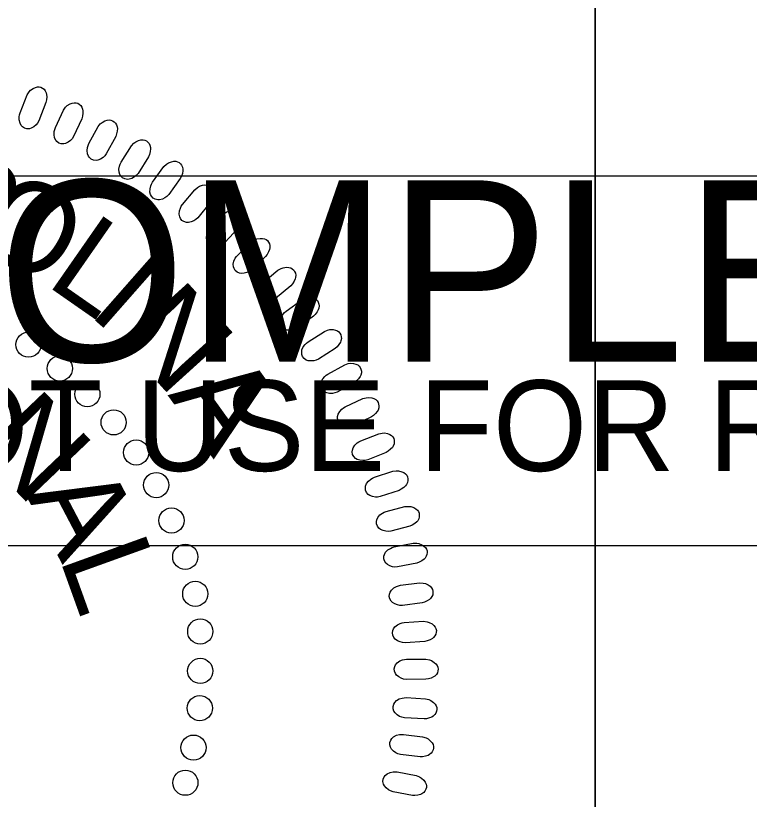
# Model space of a CAD drawing. Extents: x 505602 to 527661, y 418813 to 494436.
# Drawn here: x 507132.23 to 507178.88, y 484086.39 to 484136.19 of the extents above; entities that cross this region are included whole.
import ezdxf

# ---------------------------------------------------------------- set-up
doc = ezdxf.new("R2010")
doc.units = 0
for name, color, linetype in [('Sheet PE Seal Cell', 7, 'Continuous'), ('Sheet Profile CELL', 7, 'Continuous'), ('Sheet Sticker Incomplete CELL', 7, 'Continuous')]:
    doc.layers.add(name, color=color, linetype=linetype)

msp = doc.modelspace()

# ---------------------------------------------------------------- linework, layer by layer
at = {"layer": 'Sheet PE Seal Cell'}
for points in [[(507132.514, 484130.009), (507132.966, 484131.15), (507133.082, 484131.34), (507133.182, 484131.451), (507133.349, 484131.567), (507133.48, 484131.633), (507133.613, 484131.666), (507133.725, 484131.664), (507133.837, 484131.642), (507133.933, 484131.582), (507134.034, 484131.51), (507134.109, 484131.416), (507134.17, 484131.284), (507134.196, 484131.188), (507134.203, 484131.025), (507134.193, 484130.836), (507134.155, 484130.679), (507133.699, 484129.508), (507133.615, 484129.359), (507133.522, 484129.245), (507133.38, 484129.13), (507133.224, 484129.041), (507133.105, 484129.003), (507132.936, 484129.006), (507132.79, 484129.042), (507132.666, 484129.134), (507132.587, 484129.219), (507132.505, 484129.359), (507132.457, 484129.56), (507132.46, 484129.752), (507132.481, 484129.884)], [(507134.756, 484129.075), (507135.278, 484130.185), (507135.405, 484130.368), (507135.512, 484130.472), (507135.686, 484130.577), (507135.821, 484130.635), (507135.956, 484130.659), (507136.068, 484130.651), (507136.178, 484130.621), (507136.27, 484130.555), (507136.366, 484130.478), (507136.435, 484130.379), (507136.487, 484130.244), (507136.508, 484130.146), (507136.505, 484129.982), (507136.482, 484129.794), (507136.435, 484129.64), (507135.906, 484128.5), (507135.814, 484128.357), (507135.713, 484128.249), (507135.564, 484128.143), (507135.403, 484128.065), (507135.281, 484128.034), (507135.114, 484128.046), (507134.97, 484128.093), (507134.852, 484128.192), (507134.779, 484128.281), (507134.706, 484128.426), (507134.67, 484128.63), (507134.686, 484128.822), (507134.714, 484128.951)], [(507136.88, 484128.06), (507137.471, 484129.135), (507137.609, 484129.309), (507137.722, 484129.406), (507137.902, 484129.5), (507138.04, 484129.55), (507138.177, 484129.566), (507138.288, 484129.55), (507138.396, 484129.514), (507138.485, 484129.442), (507138.575, 484129.358), (507138.638, 484129.255), (507138.682, 484129.118), (507138.695, 484129.019), (507138.683, 484128.856), (507138.648, 484128.669), (507138.591, 484128.519), (507137.992, 484127.414), (507137.89, 484127.276), (507137.784, 484127.175), (507137.629, 484127.079), (507137.462, 484127.011), (507137.339, 484126.987), (507137.173, 484127.011), (507137.032, 484127.065), (507136.92, 484127.172), (507136.852, 484127.267), (507136.789, 484127.416), (507136.766, 484127.622), (507136.794, 484127.811), (507136.83, 484127.94)], [(507138.938, 484126.875), (507139.595, 484127.91), (507139.744, 484128.076), (507139.863, 484128.165), (507140.049, 484128.249), (507140.19, 484128.289), (507140.327, 484128.296), (507140.437, 484128.274), (507140.543, 484128.23), (507140.626, 484128.154), (507140.711, 484128.064), (507140.768, 484127.958), (507140.802, 484127.817), (507140.81, 484127.718), (507140.787, 484127.555), (507140.741, 484127.372), (507140.674, 484127.225), (507140.007, 484126.16), (507139.897, 484126.03), (507139.784, 484125.936), (507139.623, 484125.849), (507139.454, 484125.791), (507139.329, 484125.775), (507139.164, 484125.809), (507139.027, 484125.873), (507138.923, 484125.986), (507138.861, 484126.085), (507138.807, 484126.237), (507138.797, 484126.444), (507138.837, 484126.632), (507138.881, 484126.758)], [(507140.938, 484125.602), (507141.659, 484126.594), (507141.818, 484126.75), (507141.943, 484126.832), (507142.133, 484126.903), (507142.276, 484126.935), (507142.413, 484126.934), (507142.522, 484126.904), (507142.625, 484126.854), (507142.703, 484126.772), (507142.782, 484126.678), (507142.832, 484126.568), (507142.858, 484126.425), (507142.86, 484126.326), (507142.826, 484126.165), (507142.769, 484125.985), (507142.693, 484125.842), (507141.96, 484124.822), (507141.842, 484124.698), (507141.723, 484124.611), (507141.558, 484124.535), (507141.384, 484124.488), (507141.259, 484124.481), (507141.097, 484124.524), (507140.964, 484124.597), (507140.866, 484124.716), (507140.811, 484124.818), (507140.767, 484124.974), (507140.77, 484125.181), (507140.821, 484125.366), (507140.873, 484125.489)], [(507142.832, 484124.186), (507143.614, 484125.13), (507143.783, 484125.276), (507143.912, 484125.35), (507144.107, 484125.409), (507144.251, 484125.432), (507144.389, 484125.422), (507144.495, 484125.386), (507144.594, 484125.329), (507144.668, 484125.243), (507144.741, 484125.143), (507144.783, 484125.031), (507144.8, 484124.887), (507144.796, 484124.787), (507144.751, 484124.629), (507144.683, 484124.453), (507144.599, 484124.315), (507143.804, 484123.343), (507143.678, 484123.226), (507143.554, 484123.147), (507143.384, 484123.082), (507143.208, 484123.046), (507143.082, 484123.046), (507142.923, 484123.1), (507142.795, 484123.18), (507142.705, 484123.306), (507142.657, 484123.411), (507142.623, 484123.569), (507142.639, 484123.776), (507142.701, 484123.958), (507142.761, 484124.076)], [(507144.603, 484122.671), (507145.444, 484123.566), (507145.621, 484123.7), (507145.755, 484123.766), (507145.953, 484123.813), (507146.099, 484123.826), (507146.235, 484123.808), (507146.339, 484123.765), (507146.434, 484123.703), (507146.502, 484123.612), (507146.569, 484123.508), (507146.604, 484123.393), (507146.612, 484123.248), (507146.601, 484123.148), (507146.547, 484122.994), (507146.468, 484122.822), (507146.376, 484122.691), (507145.52, 484121.77), (507145.388, 484121.662), (507145.259, 484121.591), (507145.085, 484121.536), (507144.908, 484121.51), (507144.782, 484121.519), (507144.626, 484121.583), (507144.504, 484121.671), (507144.423, 484121.802), (507144.381, 484121.91), (507144.356, 484122.07), (507144.385, 484122.275), (507144.459, 484122.452), (507144.526, 484122.567)], [(507146.348, 484120.978), (507147.243, 484121.818), (507147.428, 484121.94), (507147.566, 484121.998), (507147.766, 484122.032), (507147.912, 484122.036), (507148.047, 484122.009), (507148.148, 484121.96), (507148.24, 484121.892), (507148.302, 484121.796), (507148.362, 484121.689), (507148.39, 484121.572), (507148.389, 484121.427), (507148.371, 484121.329), (507148.308, 484121.178), (507148.219, 484121.011), (507148.117, 484120.885), (507147.206, 484120.02), (507147.067, 484119.921), (507146.935, 484119.858), (507146.757, 484119.814), (507146.578, 484119.8), (507146.453, 484119.816), (507146.302, 484119.89), (507146.185, 484119.985), (507146.112, 484120.121), (507146.077, 484120.232), (507146.063, 484120.393), (507146.105, 484120.596), (507146.19, 484120.768), (507146.264, 484120.879)], [(507147.96, 484119.232), (507148.905, 484120.014), (507149.099, 484120.124), (507149.24, 484120.173), (507149.441, 484120.195), (507149.588, 484120.19), (507149.721, 484120.154), (507149.818, 484120.099), (507149.906, 484120.025), (507149.961, 484119.926), (507150.014, 484119.815), (507150.035, 484119.696), (507150.025, 484119.552), (507150.001, 484119.455), (507149.929, 484119.307), (507149.829, 484119.148), (507149.72, 484119.028), (507148.756, 484118.222), (507148.611, 484118.131), (507148.475, 484118.077), (507148.295, 484118.045), (507148.116, 484118.042), (507147.992, 484118.066), (507147.846, 484118.148), (507147.736, 484118.251), (507147.671, 484118.392), (507147.643, 484118.504), (507147.639, 484118.666), (507147.693, 484118.866), (507147.789, 484119.032), (507147.87, 484119.138)], [(507149.42, 484117.41), (507150.413, 484118.13), (507150.612, 484118.229), (507150.756, 484118.269), (507150.96, 484118.278), (507151.105, 484118.263), (507151.235, 484118.219), (507151.329, 484118.158), (507151.412, 484118.079), (507151.461, 484117.976), (507151.507, 484117.862), (507151.52, 484117.743), (507151.501, 484117.599), (507151.472, 484117.504), (507151.39, 484117.361), (507151.28, 484117.208), (507151.164, 484117.096), (507150.152, 484116.351), (507150.001, 484116.27), (507149.861, 484116.224), (507149.68, 484116.203), (507149.501, 484116.212), (507149.379, 484116.244), (507149.239, 484116.335), (507149.135, 484116.445), (507149.079, 484116.589), (507149.058, 484116.703), (507149.064, 484116.865), (507149.131, 484117.061), (507149.237, 484117.221), (507149.324, 484117.321)], [(507150.821, 484115.463), (507151.857, 484116.12), (507152.062, 484116.206), (507152.208, 484116.237), (507152.411, 484116.234), (507152.556, 484116.21), (507152.683, 484116.158), (507152.773, 484116.091), (507152.85, 484116.007), (507152.893, 484115.902), (507152.932, 484115.784), (507152.938, 484115.664), (507152.909, 484115.522), (507152.874, 484115.429), (507152.783, 484115.292), (507152.664, 484115.145), (507152.542, 484115.041), (507151.485, 484114.362), (507151.329, 484114.29), (507151.187, 484114.253), (507151.004, 484114.243), (507150.826, 484114.263), (507150.707, 484114.303), (507150.572, 484114.403), (507150.476, 484114.519), (507150.429, 484114.666), (507150.415, 484114.781), (507150.431, 484114.942), (507150.51, 484115.134), (507150.626, 484115.287), (507150.72, 484115.382)], [(507152.082, 484113.413), (507153.157, 484114.004), (507153.367, 484114.077), (507153.515, 484114.099), (507153.717, 484114.082), (507153.86, 484114.05), (507153.984, 484113.989), (507154.07, 484113.917), (507154.141, 484113.828), (507154.178, 484113.72), (507154.209, 484113.601), (507154.207, 484113.481), (507154.17, 484113.341), (507154.129, 484113.25), (507154.03, 484113.119), (507153.901, 484112.981), (507153.773, 484112.884), (507152.675, 484112.272), (507152.515, 484112.21), (507152.371, 484112.182), (507152.188, 484112.185), (507152.012, 484112.215), (507151.895, 484112.262), (507151.767, 484112.371), (507151.678, 484112.492), (507151.641, 484112.642), (507151.634, 484112.758), (507151.66, 484112.918), (507151.751, 484113.104), (507151.876, 484113.25), (507151.976, 484113.338)], [(507153.189, 484111.33), (507154.299, 484111.853), (507154.514, 484111.912), (507154.662, 484111.925), (507154.864, 484111.895), (507155.004, 484111.853), (507155.124, 484111.786), (507155.205, 484111.708), (507155.271, 484111.615), (507155.3, 484111.505), (507155.324, 484111.384), (507155.315, 484111.264), (507155.269, 484111.127), (507155.222, 484111.039), (507155.115, 484110.914), (507154.978, 484110.784), (507154.843, 484110.696), (507153.709, 484110.154), (507153.546, 484110.103), (507153.4, 484110.084), (507153.219, 484110.097), (507153.044, 484110.139), (507152.93, 484110.193), (507152.809, 484110.31), (507152.728, 484110.437), (507152.7, 484110.588), (507152.701, 484110.705), (507152.737, 484110.862), (507152.84, 484111.042), (507152.974, 484111.18), (507153.079, 484111.262)], [(507154.169, 484109.169), (507155.31, 484109.621), (507155.527, 484109.666), (507155.676, 484109.67), (507155.875, 484109.628), (507156.013, 484109.577), (507156.128, 484109.502), (507156.204, 484109.42), (507156.264, 484109.323), (507156.286, 484109.211), (507156.302, 484109.089), (507156.286, 484108.97), (507156.231, 484108.835), (507156.179, 484108.751), (507156.065, 484108.633), (507155.92, 484108.511), (507155.78, 484108.432), (507154.614, 484107.963), (507154.448, 484107.921), (507154.301, 484107.912), (507154.12, 484107.936), (507153.949, 484107.989), (507153.839, 484108.05), (507153.725, 484108.174), (507153.652, 484108.306), (507153.634, 484108.46), (507153.642, 484108.575), (507153.688, 484108.73), (507153.802, 484108.904), (507153.944, 484109.033), (507154.054, 484109.108)], [(507155.042, 484106.855), (507156.21, 484107.234), (507156.43, 484107.266), (507156.579, 484107.26), (507156.775, 484107.205), (507156.909, 484107.147), (507157.02, 484107.065), (507157.09, 484106.978), (507157.143, 484106.877), (507157.159, 484106.764), (507157.168, 484106.641), (507157.143, 484106.523), (507157.08, 484106.393), (507157.023, 484106.311), (507156.901, 484106.2), (507156.749, 484106.089), (507156.604, 484106.018), (507155.411, 484105.623), (507155.243, 484105.592), (507155.097, 484105.592), (507154.918, 484105.628), (507154.75, 484105.691), (507154.644, 484105.759), (507154.538, 484105.89), (507154.473, 484106.026), (507154.465, 484106.181), (507154.48, 484106.295), (507154.536, 484106.447), (507154.66, 484106.613), (507154.81, 484106.733), (507154.924, 484106.801)], [(507155.788, 484104.682), (507156.976, 484104.986), (507157.197, 484105.005), (507157.346, 484104.989), (507157.538, 484104.923), (507157.669, 484104.856), (507157.773, 484104.767), (507157.838, 484104.676), (507157.885, 484104.572), (507157.894, 484104.458), (507157.894, 484104.335), (507157.863, 484104.219), (507157.792, 484104.093), (507157.73, 484104.015), (507157.601, 484103.913), (507157.442, 484103.81), (507157.293, 484103.748), (507156.078, 484103.429), (507155.908, 484103.409), (507155.762, 484103.418), (507155.585, 484103.465), (507155.422, 484103.538), (507155.32, 484103.613), (507155.224, 484103.75), (507155.167, 484103.89), (507155.169, 484104.045), (507155.191, 484104.158), (507155.256, 484104.306), (507155.39, 484104.464), (507155.548, 484104.574), (507155.666, 484104.635)], [(507156.297, 484102.428), (507157.502, 484102.657), (507157.725, 484102.661), (507157.872, 484102.637), (507158.059, 484102.558), (507158.185, 484102.483), (507158.285, 484102.388), (507158.343, 484102.293), (507158.384, 484102.186), (507158.385, 484102.072), (507158.378, 484101.949), (507158.339, 484101.835), (507158.261, 484101.714), (507158.194, 484101.64), (507158.059, 484101.546), (507157.894, 484101.454), (507157.742, 484101.402), (507156.508, 484101.159), (507156.337, 484101.15), (507156.192, 484101.168), (507156.019, 484101.226), (507155.861, 484101.31), (507155.764, 484101.39), (507155.675, 484101.534), (507155.628, 484101.677), (507155.639, 484101.831), (507155.669, 484101.943), (507155.743, 484102.087), (507155.887, 484102.235), (507156.052, 484102.336), (507156.173, 484102.389)], [(507156.695, 484099.989), (507157.913, 484100.141), (507158.135, 484100.132), (507158.28, 484100.098), (507158.462, 484100.008), (507158.584, 484099.925), (507158.677, 484099.824), (507158.729, 484099.725), (507158.763, 484099.617), (507158.757, 484099.503), (507158.742, 484099.38), (507158.696, 484099.268), (507158.61, 484099.153), (507158.539, 484099.084), (507158.398, 484098.998), (507158.228, 484098.916), (507158.072, 484098.873), (507156.826, 484098.709), (507156.655, 484098.711), (507156.511, 484098.738), (507156.342, 484098.806), (507156.189, 484098.9), (507156.098, 484098.987), (507156.018, 484099.135), (507155.981, 484099.281), (507156.002, 484099.434), (507156.038, 484099.544), (507156.121, 484099.683), (507156.274, 484099.822), (507156.444, 484099.911), (507156.569, 484099.957)], [(507156.939, 484097.624), (507158.163, 484097.7), (507158.384, 484097.676), (507158.527, 484097.634), (507158.704, 484097.532), (507158.819, 484097.442), (507158.905, 484097.335), (507158.951, 484097.233), (507158.979, 484097.122), (507158.966, 484097.009), (507158.944, 484096.888), (507158.89, 484096.78), (507158.797, 484096.669), (507158.721, 484096.605), (507158.576, 484096.528), (507158.401, 484096.457), (507158.243, 484096.425), (507156.989, 484096.339), (507156.819, 484096.351), (507156.676, 484096.387), (507156.512, 484096.466), (507156.366, 484096.569), (507156.28, 484096.661), (507156.21, 484096.814), (507156.181, 484096.963), (507156.211, 484097.114), (507156.255, 484097.222), (507156.346, 484097.355), (507156.508, 484097.484), (507156.683, 484097.563), (507156.81, 484097.601)], [(507157.088, 484095.294), (507158.315, 484095.293), (507158.534, 484095.255), (507158.674, 484095.203), (507158.844, 484095.091), (507158.953, 484094.994), (507159.033, 484094.882), (507159.072, 484094.777), (507159.092, 484094.665), (507159.072, 484094.553), (507159.043, 484094.433), (507158.983, 484094.329), (507158.883, 484094.224), (507158.803, 484094.164), (507158.653, 484094.097), (507158.474, 484094.037), (507158.315, 484094.015), (507157.058, 484094.007), (507156.889, 484094.03), (507156.748, 484094.076), (507156.589, 484094.165), (507156.45, 484094.277), (507156.37, 484094.374), (507156.31, 484094.531), (507156.29, 484094.681), (507156.33, 484094.83), (507156.38, 484094.935), (507156.479, 484095.062), (507156.65, 484095.181), (507156.829, 484095.249), (507156.958, 484095.279)], [(507157.055, 484092.853), (507158.28, 484092.776), (507158.495, 484092.724), (507158.632, 484092.664), (507158.795, 484092.541), (507158.898, 484092.437), (507158.97, 484092.32), (507159.003, 484092.213), (507159.016, 484092.099), (507158.989, 484091.989), (507158.952, 484091.872), (507158.886, 484091.771), (507158.779, 484091.673), (507158.696, 484091.618), (507158.542, 484091.56), (507158.359, 484091.512), (507158.198, 484091.5), (507156.944, 484091.572), (507156.776, 484091.605), (507156.64, 484091.659), (507156.486, 484091.758), (507156.354, 484091.879), (507156.28, 484091.981), (507156.23, 484092.141), (507156.22, 484092.292), (507156.269, 484092.438), (507156.326, 484092.54), (507156.433, 484092.66), (507156.61, 484092.769), (507156.794, 484092.825), (507156.924, 484092.846)], [(507156.888, 484090.513), (507158.106, 484090.359), (507158.318, 484090.294), (507158.45, 484090.225), (507158.605, 484090.092), (507158.702, 484089.982), (507158.766, 484089.861), (507158.793, 484089.752), (507158.798, 484089.638), (507158.765, 484089.53), (507158.719, 484089.415), (507158.647, 484089.319), (507158.535, 484089.227), (507158.449, 484089.178), (507158.292, 484089.13), (507158.106, 484089.093), (507157.945, 484089.091), (507156.697, 484089.242), (507156.532, 484089.285), (507156.399, 484089.347), (507156.252, 484089.456), (507156.128, 484089.585), (507156.061, 484089.691), (507156.021, 484089.855), (507156.02, 484090.005), (507156.079, 484090.149), (507156.141, 484090.246), (507156.256, 484090.36), (507156.439, 484090.457), (507156.626, 484090.502), (507156.758, 484090.514)], [(507156.492, 484088.126), (507157.696, 484087.895), (507157.905, 484087.818), (507158.032, 484087.741), (507158.178, 484087.598), (507158.267, 484087.482), (507158.325, 484087.357), (507158.344, 484087.247), (507158.343, 484087.133), (507158.302, 484087.027), (507158.25, 484086.915), (507158.172, 484086.823), (507158.054, 484086.739), (507157.964, 484086.695), (507157.805, 484086.657), (507157.618, 484086.632), (507157.457, 484086.64), (507156.221, 484086.869), (507156.059, 484086.923), (507155.93, 484086.993), (507155.79, 484087.111), (507155.674, 484087.247), (507155.614, 484087.357), (507155.584, 484087.523), (507155.593, 484087.674), (507155.66, 484087.813), (507155.729, 484087.907), (507155.85, 484088.013), (507156.039, 484088.098), (507156.229, 484088.131), (507156.361, 484088.135)]]:
    msp.add_lwpolyline(points, close=True, dxfattribs=at)
for centre in [(507133.046, 484115.283), (507135.036, 484113.769), (507136.787, 484112.135), (507138.459, 484110.342), (507139.891, 484108.429), (507141.165, 484106.357), (507142.137, 484104.108), (507143.012, 484101.797), (507143.648, 484099.446), (507143.966, 484097.056), (507143.965, 484094.546), (507143.935, 484092.183), (507143.537, 484089.673), (507143.018, 484087.442)]:
    msp.add_circle(centre, 0.801, dxfattribs=at)
at = {"layer": 'Sheet Profile CELL'}
msp.add_line((507169.08, 484158.662), (507169.08, 484046.212), dxfattribs=at)
for points in [[(507069.03, 484158.662), (507169.08, 484158.662), (507169.08, 484046.162), (507069.03, 484046.162)], [(507169.08, 484158.662), (507269.08, 484158.662), (507269.08, 484046.162), (507169.08, 484046.162)]]:
    msp.add_lwpolyline(points, close=True, dxfattribs=at)
at = {"layer": 'Sheet Sticker Incomplete CELL'}
msp.add_lwpolyline([(507095.597, 484102.505), (507095.597, 484126.005), (507242.597, 484126.005), (507242.597, 484102.505)], close=True, dxfattribs=at)

# ---------------------------------------------------------------- texts
at = {"layer": 'Sheet PE Seal Cell'}
for s, rotation, p in [('R', 344.609, (507126.371, 484122.32)), ('O', 331.6302, (507129.326, 484121.666)), ('L', 325.1409, (507134.059, 484119.135)), ('I', 318.6515, (507136.752, 484117.282)), ('N', 312.1622, (507138.557, 484115.862)), ('A', 305.6728, (507141.877, 484112.082)), ('N', 313.6502, (507129.525, 484108.823)), ('A', 297.7707, (507132.862, 484105.743)), ('L', 289.8309, (507134.985, 484101.748))]:
    msp.add_text(s, height=5.669, rotation=rotation, dxfattribs=at).set_placement(p)
at = {"layer": 'Sheet Sticker Incomplete CELL'}
for s, height, p in [('INCOMPLETE PLANS', 11.52, (507104.547, 484114.205)), ('DO NOT USE FOR R/W ACQUISITION', 5.76, (507107.797, 484107.255))]:
    msp.add_text(s, height=height, dxfattribs=at).set_placement(p)

doc.saveas('drawing.dxf')
